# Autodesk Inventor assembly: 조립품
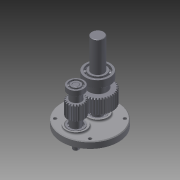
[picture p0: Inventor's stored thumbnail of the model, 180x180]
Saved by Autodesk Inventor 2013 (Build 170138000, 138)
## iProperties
Created: 2015-07
Part Number: 조립품
Document SubType Name: Assembly
Designer: user
Author: user
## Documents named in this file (9)
- C:\Users\user\Desktop\450734V1001\조립품.iam
- C:\Users\user\Desktop\450734V1001\본체.ipt
- C:\Users\user\Desktop\450734V1001\베어링 6003.ipt
- 베어링 6003.ipt
- C:\Users\user\Desktop\450734V1001\베어링 608.ipt
- 베어링 608.ipt
- C:\Users\user\Desktop\450734V1001\서브축.ipt
- C:\Users\user\Desktop\450734V1001\메인축.ipt
- C:\Users\user\Desktop\450734V1001\커버.ipt
